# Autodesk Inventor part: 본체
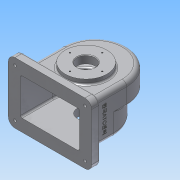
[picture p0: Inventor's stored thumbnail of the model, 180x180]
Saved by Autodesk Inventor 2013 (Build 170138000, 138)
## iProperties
Created: 2017-11
Part Number: 본체
Material: 알루미늄 6061
Document SubType Name: Modeling
Designer: Administrator
Density: 2.71 g/cm^3
Mass: 1079.55 g
Surface Area: 1182 cm^2
Volume: 398.359 cm^3
Author: Administrator
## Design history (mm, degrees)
sketch "스케치1"
  geometry: L1 (-58, 0)-(-58, -80); L2 (58, 0)-(58, -80); L3 (-58, -80)-(58, -80); L4 (-75, -65)-(75, -65); L5 (75, -65)-(75, -80); L6 (75, -80)-(-75, -80); L7 (-75, -80)-(-75, -65); A1 r 58 centre (0, 0) between (58, 0) and (-58, 0); 4 further points
  constraints: 14 end point, 4 parallel, 3 midpoint, 2 coincident, 2 perpendicular, 2 point on circle, 2 tangent, 1 centre point, 1 horizontal, 1 vertical, 1 vertical alignment
  dimensions: "d0" = 116 diameter of A1; "d1" = 80 distance of L2.start L2.end; "d9" = 150 distance of L5.end L6.end; "d10" = 15 distance of L6.end L4.start
extrude "돌출1" new body sketch "스케치1" distance "d2" = 38; taper "d3" = 0 deg
sketch "스케치2"
  geometry: L1 (-58, 0)-(-58, -80) reference; L2 (-58, -80)-(58, -80) reference; L3 (58, -80)-(58, 0) reference; L4 (58, -23)-(58, -80); L5 (-58, -80)-(-58, -23); A1 r 58 centre (0, 0) between (58, 0) and (-58, 0) reference; A2 r 58 centre (0, -23) between (58, -23) and (-58, -23)
  constraints: 4 end point, 2 point on circle, 2 point on line, 1 centre point, 1 collinear, 1 vertical alignment
  dimensions: "d4" = 116 diameter of A2; "d6" = 57 distance from line of L2 A2.centre
extrude "돌출2" join sketch "스케치2" distance "d7" = 38; taper "d8" = 0 deg
feature "쉘1" dims "d15" = 5
extrude "돌출3" join sketch "스케치1" distance "d11" = 17; taper "d13" = 0 deg; dims "d12" = 93, "d14" = 0
sketch "스케치3"
  geometry: L1 (128, -88)-(128, -22) reference; L2 (128, -22)-(22, -22) reference; L3 (22, -22)-(22, -88) reference; L4 (22, -88)-(128, -88) reference; 1 further point
extrude "돌출4" cut sketch "스케치3" distance "d16" = 15; taper "d17" = 0 deg
sketch "스케치4"
  geometry: L1 (-75, -80)-(75, -80) reference; C1 r 37.5 at (0, -15); A1 r 58 centre (0, 0) between (58, 0) and (-58, 0) reference
  constraints: 1 centre point, 1 vertical alignment
  dimensions: "d18" = 75 diameter of C1; "d20" = 65 distance from line of L1 C1.centre
extrude "돌출5" join sketch "스케치4" distance "d21" = 9; taper "d22" = 0 deg
sketch "스케치5"
  geometry: L1 (-75, -80)-(75, -80) reference; C1 r 31 at (0, -15); 1 further point
  constraints: 1 centre point, 1 vertical alignment
  dimensions: "d23" = 62 diameter of C1; "d25" = 65 distance from line of C1.centre L1
extrude "돌출6" join sketch "스케치5" distance "d26" = 10; taper "d27" = 0 deg
hole "구멍1" diameter "d30" = 32; stored, may be unused: countersink angle "d34" = 90 deg, drill point angle "d36" = 118 deg; dims "d28" = 10, "d29" = 10, "d31" = 6, "d32" = 4, "d33" = 2, "d35" = 8
sketch "스케치6"
  geometry: C1 r 16 at (0, 0) reference; 2 further points
  constraints: 1 vertical alignment
  dimensions: "d37" = 29 distance of C1.centre point (0, 29)
hole "구멍2" sketch "스케치6" at (0, 29) diameter "d38" = 2.459; stored, may be unused: countersink angle "d42" = 90 deg, drill point angle "d44" = 118 deg; dims "d39" = 6, "d40" = 4, "d41" = 2, "d43" = 8
sketch "스케치7"
  geometry: C1 r 16 at (0, 0) reference; 2 further points
  constraints: 1 vertical alignment
  dimensions: "d48" = 26 distance of C1.centre point (0, 26)
hole "구멍3" sketch "스케치7" at (0, 26) diameter "d49" = 2.459; stored, may be unused: countersink angle "d53" = 90 deg, drill point angle "d55" = 118 deg; dims "d50" = 6, "d51" = 4, "d52" = 2, "d54" = 8
fillet "모깎기1" dims "d59" = 3
fillet "모깎기3" dims "d61" = 12, "d62" = 8
fillet "모깎기2" dims "d60" = 3
sketch "스케치8"
  geometry: A1 r 9 centre (126, 9) between (126, 0) and (135, 9) reference; A2 r 9 centre (126, 95) between (135, 95) and (126, 104) reference; A3 r 9 centre (0, 95) between (0, 104) and (-9, 95) reference; A4 r 9 centre (0, 9) between (-9, 9) and (0, 0) reference; 1 further point
hole "구멍4" sketch "스케치8" at (0, 95), (126, 9), (126, 95), (0, 9) diameter "d63" = 5; stored, may be unused: countersink angle "d67" = 90 deg, drill point angle "d69" = 118 deg; dims "d64" = 6, "d65" = 12, "d66" = 5, "d68" = 8
node "작업 평면1"
sketch "스케치9"
  geometry: C1 r 6 at (0, -19); 1 further point
  constraints: 1 centre point, 1 vertical alignment
  dimensions: "d71" = 12 diameter of C1; "d73" = 19 distance of C1.centre point (0, 0)
extrude "돌출7" join sketch "스케치9" stored distance "d74" = 10; taper "d75" = 0 deg
hole "구멍5" diameter "d78" = 4.134; stored, may be unused: countersink angle "d82" = 90 deg, drill point angle "d84" = 118 deg; dims "d76" = 10, "d77" = 10, "d79" = 6, "d80" = 12, "d81" = 5, "d83" = 8
fillet "모깎기4" dims "d85" = 3
chamfer "모따기1" distance "d86" = 1; stored, may be unused: second distance "d87" = 2, angle "d88" = 45 deg
sketch "스케치10"
  geometry: L1 (-13, -80)-(-25, -80) reference; L2 (-8, 0)-(-8, -62) reference; 1 further point
  constraints: 1 other
  dimensions: "d89" = 40 distance from line of L1 point (30, -40); "d90" = 38 distance from line of point (30, -40) L2
feature "엠보싱1" sketch "스케치10" dims "d0" = 116, "d1" = 80, "d9" = 150, "d10" = 15, "d91" = 0.5, "d92" = 0
node "솔리드1"
pattern_circular "원형 패턴1" dims angle "d46" = 360 deg
pattern_circular "원형 패턴2" dims angle "d57" = 360 deg
other parameters: "d70" = 64
